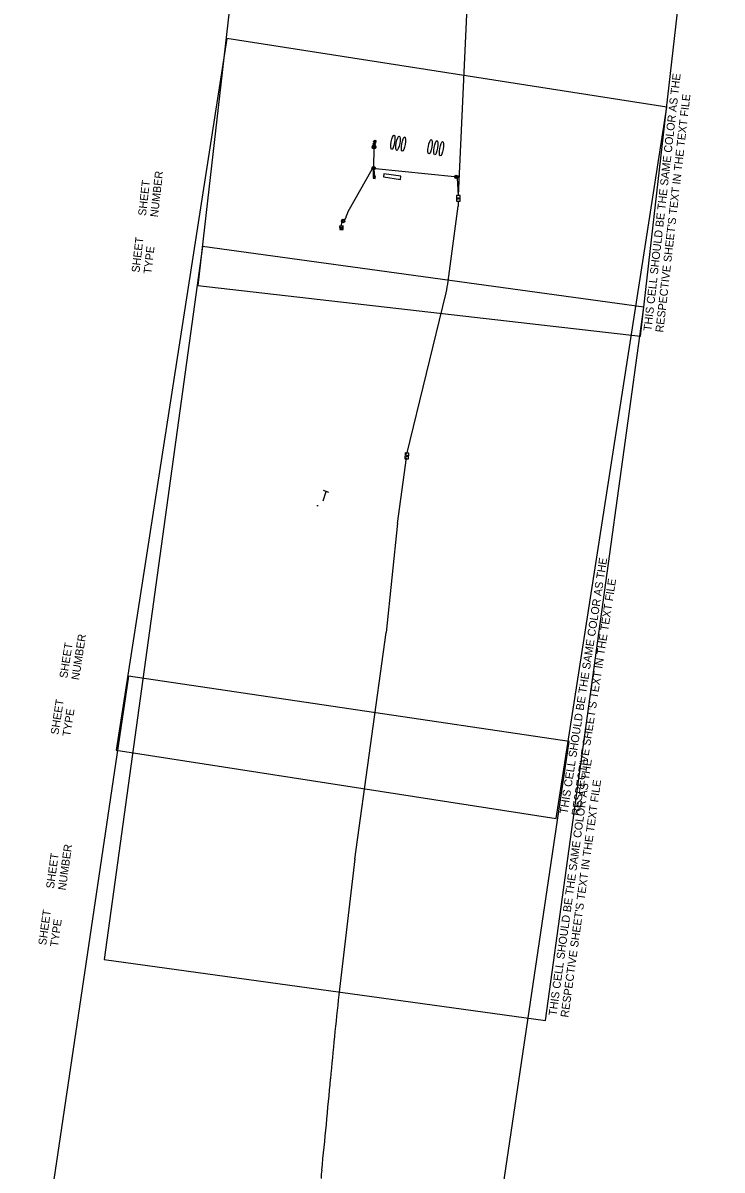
# Model space of a CAD drawing. Extents: x 601462 to 605493, y 331960 to 402715.
# Drawn here: x 601939 to 603469, y 358810 to 361319 of the extents above; entities that cross this region are included whole.
import ezdxf

# ---------------------------------------------------------------- set-up
doc = ezdxf.new("R2010")
doc.units = 0
for name, color, linetype in [('P_FTMS', 7, 'Continuous'), ('P_FTMSConduit', 7, 'Continuous'), ('P_MISC_TXT_1A (Construction)', 7, 'Continuous'), ('P_MISC_TXT_1B (Construction)', 7, 'Continuous'), ('P_MISC_TXT_2A (Construction)', 7, 'Continuous'), ('P_MISC_TXT_2B (Construction)', 7, 'Continuous')]:
    doc.layers.add(name, color=color, linetype=linetype)

# ---------------------------------------------------------------- blocks, each defined once
blk = doc.blocks.new('FTMS_FCV')
at = {"layer": 'P_FTMS'}
blk.add_line((13, 16), (1, -22), dxfattribs=at)
blk.add_lwpolyline([(39, 24), (-39, 24), (-39, -24), (39, -24)], close=True, dxfattribs=at)
blk.add_lwpolyline([(-12, 16), (1, -22)], dxfattribs=at)
blk = doc.blocks.new('FMB')
at = {"layer": 'P_FTMS'}
for p, q in [((24, -24), (-24, 24)), ((-24, -24), (24, 24))]:
    blk.add_line(p, q, dxfattribs=at)
blk.add_lwpolyline([(24, -24), (24, 24), (-24, 24), (-24, -24)], close=True, dxfattribs=at)
blk = doc.blocks.new('FMB_1')
at = {"layer": 'P_FTMS'}
for p, q in [((24, -24), (-24, 24)), ((-24, -24), (24, 24))]:
    blk.add_line(p, q, dxfattribs=at)
blk.add_lwpolyline([(24, -24), (24, 24), (-24, 24), (-24, -24)], close=True, dxfattribs=at)
blk = doc.blocks.new('_U238')
at = {"layer": 'P_FTMS'}
for points in [[(-15, -7), (7, -15), (0, 0)], [(15, 7), (-7, 15), (0, 0)]]:
    blk.add_lwpolyline(points, close=True, dxfattribs=at)
at = {"layer": 'P_FTMS', "xscale": 0.47132639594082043, "yscale": 0.4713263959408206, "rotation": 70.39802054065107}
blk.add_blockref('FMB_1', (0, 0), dxfattribs=at)
blk = doc.blocks.new('FTMS_FERA')
at = {"layer": 'P_FTMS'}
for p, q in [((-65, 37), (-65, -37)), ((65, 0), (-65, 0))]:
    blk.add_line(p, q, dxfattribs=at)
blk = doc.blocks.new('FMD')
at = {"layer": 'P_FTMS'}
for p, q in [((17, 18), (-17, 18)), ((-16, 16), (-16, 18)), ((16, 16), (-16, 16)), ((-15, 15), (-15, 20)), ((15, 19), (-15, 19)), ((15, 15), (-15, 15)), ((14, 20), (-14, 20)), ((13, 22), (-13, 22)), ((-13, 13), (-13, 21)), ((13, 13), (-13, 13)), ((-12, 12), (-12, 23)), ((12, 12), (-12, 12)), ((11, 23), (-11, 23)), ((10, 25), (-10, 25)), ((-10, 10), (-10, 24)), ((10, 10), (-10, 10)), ((-9, 9), (-9, 26)), ((9, 9), (-9, 9)), ((8, 26), (-8, 26)), ((7, 28), (-7, 28)), ((-7, 7), (-7, 27)), ((7, 7), (-7, 7)), ((-6, 6), (-6, 29)), ((6, 6), (-6, 6)), ((5, 29), (-5, 29)), ((4, 31), (-4, 31)), ((-4, 4), (-4, 30)), ((4, 4), (-4, 4)), ((-3, 3), (-3, 32)), ((3, 3), (-3, 3)), ((2, 32), (-2, 32)), ((1, 34), (-1, 34)), ((-1, 1), (-1, 33)), ((1, 1), (-1, 1)), ((0, 0), (0, 34)), ((1, 1), (1, 33)), ((3, 3), (3, 32)), ((4, 4), (4, 30)), ((6, 6), (6, 29)), ((7, 7), (7, 27)), ((9, 9), (9, 26)), ((10, 10), (10, 24)), ((12, 12), (12, 23)), ((13, 13), (13, 21)), ((15, 15), (15, 20)), ((16, 16), (16, 18))]:
    blk.add_line(p, q, dxfattribs=at)
blk.add_lwpolyline([(-17, 17), (0, 34), (17, 17), (0, 0)], close=True, dxfattribs=at)

msp = doc.modelspace()

# ---------------------------------------------------------------- linework, layer by layer
at = {"layer": 'P_FTMS'}
for p, q in [((602705.2, 361051.2), (602703.6, 361047.2)), ((602704.8, 361050.9), (602703.6, 361047.7)), ((602705.6, 361051.4), (602703.7, 361046.8)), ((602705.9, 361051.6), (602703.8, 361046.4)), ((602706.2, 361051.7), (602704, 361046.1)), ((602706.5, 361051.8), (602704.1, 361045.9)), ((602706.8, 361051.9), (602704.3, 361045.6)), ((602707.1, 361051.9), (602704.5, 361045.4)), ((602707.3, 361051.9), (602704.6, 361045.2)), ((602707.6, 361051.9), (602704.8, 361045)), ((602711.5, 361048.2), (602704.8, 361050.8)), ((602707.8, 361051.9), (602705, 361044.9)), ((602711.5, 361048.4), (602705, 361051)), ((602708.1, 361051.9), (602705.2, 361044.7)), ((602711.5, 361048.7), (602705.2, 361051.2)), ((602708.3, 361051.9), (602705.4, 361044.6)), ((602711.4, 361049), (602705.5, 361051.4)), ((602708.6, 361051.8), (602705.6, 361044.4)), ((602711.3, 361049.3), (602705.7, 361051.5)), ((602708.8, 361051.7), (602705.8, 361044.3)), ((602709, 361051.7), (602706.1, 361044.2)), ((602711.2, 361049.6), (602706.1, 361051.6)), ((602709.2, 361051.6), (602706.3, 361044.1)), ((602711, 361049.9), (602706.4, 361051.8)), ((602709.5, 361051.4), (602706.5, 361044.1)), ((602710.8, 361050.3), (602706.8, 361051.9)), ((602709.7, 361051.3), (602706.8, 361044)), ((602709.9, 361051.2), (602707, 361044)), ((602710.5, 361050.7), (602707.3, 361051.9)), ((602710.1, 361051), (602707.3, 361044)), ((602710.3, 361050.9), (602707.5, 361044)), ((602710, 361051.1), (602708, 361051.9)), ((602704.4, 361050.4), (602703.6, 361048.3)), ((602710.9, 361045.8), (602703.6, 361048.7)), ((602710.8, 361045.6), (602703.6, 361048.5)), ((602710.6, 361045.4), (602703.6, 361048.2)), ((602710.5, 361045.2), (602703.6, 361048)), ((602710.3, 361045), (602703.6, 361047.7)), ((602710.1, 361044.9), (602703.6, 361047.5)), ((602709.9, 361044.7), (602703.6, 361047.2)), ((602711.1, 361046), (602703.7, 361049)), ((602709.6, 361044.5), (602703.7, 361046.9)), ((602711.3, 361046.5), (602703.8, 361049.4)), ((602711.2, 361046.2), (602703.8, 361049.2)), ((602709.3, 361044.4), (602703.8, 361046.6)), ((602711.3, 361046.7), (602703.9, 361049.6)), ((602709.1, 361044.2), (602703.9, 361046.3)), ((602711.4, 361046.9), (602704.1, 361049.9)), ((602708.7, 361044.1), (602704.1, 361046)), ((602711.5, 361047.2), (602704.2, 361050.1)), ((602711.5, 361047.4), (602704.3, 361050.3)), ((602708.3, 361044), (602704.3, 361045.6)), ((602711.5, 361047.6), (602704.5, 361050.5)), ((602711.5, 361047.9), (602704.6, 361050.7)), ((602707.8, 361044), (602704.6, 361045.2)), ((602707.1, 361044), (602705.1, 361044.8)), ((602710.4, 361050.7), (602707.8, 361044)), ((602710.6, 361050.5), (602708, 361044)), ((602710.8, 361050.3), (602708.3, 361044)), ((602711, 361050), (602708.6, 361044.1)), ((602711.1, 361049.7), (602708.9, 361044.2)), ((602711.2, 361049.4), (602709.2, 361044.3)), ((602711.4, 361049.1), (602709.5, 361044.5)), ((602711.5, 361048.7), (602709.9, 361044.7)), ((602711.5, 361048.2), (602710.3, 361045)), ((602711.5, 361047.5), (602710.7, 361045.5)), ((602729.5, 360989.2), (602728.5, 360982.4)), ((602728.5, 360982.4), (602765.6, 360977.2)), ((602766.6, 360984.1), (602729.5, 360989.2)), ((602765.6, 360977.2), (602766.6, 360984.1))]:
    msp.add_line(p, q, dxfattribs=at)
msp.add_lwpolyline([(602728.5, 360982.4), (602765.6, 360977.2), (602766.6, 360984.1), (602729.5, 360989.2)], close=True, dxfattribs=at)
for centre, radius in [((602707.5, 361047.9), 4), ((602706.9, 361001.6), 3.75), ((602887.8, 360982.5), 3.75), ((602640.1, 360886.1), 3.75)]:
    msp.add_circle(centre, radius, dxfattribs=at)
for centre, start, end in [((602706.6, 360997.2), 32.6299, 138.8855), ((602707.3, 361006.1), 212.6299, 318.8855), ((602887.4, 360978), 32.6299, 138.8855), ((602888.1, 360987), 212.6299, 318.8855), ((602639.8, 360881.7), 32.6299, 138.8855), ((602640.5, 360890.6), 212.6299, 318.8855)]:
    msp.add_arc(centre, 3.75, start, end, dxfattribs=at)
for centre in [(602749, 361058.3), (602760.2, 361056.3), (602772.1, 361054.3), (602830.3, 361048.5), (602843, 361046.3), (602855.2, 361044.2)]:
    msp.add_ellipse(centre, major_axis=(-2.7, -15.7), ratio=0.23471, dxfattribs=at)
at = {"layer": 'P_FTMSConduit'}
for p, q in [((602707.4, 361005.6), (602707.7, 361043.9)), ((602710.7, 361001.3), (602884.2, 360983.5)), ((602706.2, 360998), (602705.5, 360982.9)), ((602707.3, 360997.9), (602708.7, 360984)), ((602892.8, 360942.1), (602890.6, 360980)), ((602636.3, 360875.3), (602637, 360884.1)), ((602758.9, 360224.5), (602778.7, 360367.9)), ((602585.7, 360263.4), (602582.6, 360263.1)), ((602758.9, 360224.9), (602734.1, 359986.4)), ((602665.6, 359490.5), (602734, 359985.8)), ((602665.7, 359490.9), (602630.7, 359193.4))]:
    msp.add_line(p, q, dxfattribs=at)
for points in [[(602892.8, 360942.1), (602911.3, 361353.5)], [(602650.9, 360907.2), (602703.8, 360999.6)], [(602892.4, 360930.1), (602892.4, 360929.2)], [(602870.2, 360754.7), (602892.2, 360918.3)], [(602779.4, 360375.8), (602865.3, 360729)]]:
    msp.add_lwpolyline(points, dxfattribs=at)
for centre, radius, start, end in [((602842.7, 360925), 50, 352.3262, 5.9193), ((602577.6, 360925.5), 75.6, 330.3744, 345.9697), ((602622.4, 360788.1), 250, 346.3228, 352.3262), ((610662.2, 358306.9), 8080.3, 173.70013, 175.00722), ((591535.1, 359977.9), 11119.7, 353.9728, 355.00722), ((602671.7, 358796.8), 79.5, 170.2547, 183.3334)]:
    msp.add_arc(centre, radius, start, end, dxfattribs=at)
at = {"layer": 'P_MISC_TXT_1A (Construction)'}
msp.add_lwpolyline([(603290.7, 360634.3), (603469.4, 362199.1), (602500.7, 362309.8), (602322, 360745)], close=True, dxfattribs=at)
at = {"layer": 'P_MISC_TXT_1B (Construction)'}
msp.add_lwpolyline([(603082.7, 359137.1), (603298.3, 360697.3), (602332.5, 360830.7), (602116.9, 359270.6)], close=True, dxfattribs=at)
at = {"layer": 'P_MISC_TXT_2A (Construction)'}
msp.add_lwpolyline([(602903.8, 358189.7), (603134.9, 359747.6), (602170.5, 359890.7), (601939.4, 358332.8)], close=True, dxfattribs=at)
at = {"layer": 'P_MISC_TXT_2B (Construction)'}
msp.add_lwpolyline([(603106.7, 359579), (603348.9, 361135.2), (602385.5, 361285.2), (602143.3, 359728.9)], close=True, dxfattribs=at)

# ---------------------------------------------------------------- block references
at = {"layer": 'P_FTMS'}
for name, p, xscale, yscale, rotation in [('FMD', (602705.6, 361055), 0.16404166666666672, 0.16404166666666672, -101.0974780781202), ('FMD', (602706.7, 361060.5), 0.16404166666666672, 0.16404166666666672, -101.0974780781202), ('_U238', (602708.4, 360981.7), 0.19684999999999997, 0.19684999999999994, 11.744108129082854), ('FTMS_FCV', (602892.5, 360935.7), 0.16404166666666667, 0.16404166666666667, 90.21124366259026), ('FMB', (602636.4, 360871.3), 0.16404166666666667, 0.16404166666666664, 91.21445292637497), ('FTMS_FCV', (602779.3, 360372.4), 0.1640416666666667, 0.16404166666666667, 86.34463929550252), ('FTMS_FERA', (602600, 360284.3), 0.16404166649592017, 0.16404143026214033, -107.86745926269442)]:
    msp.add_blockref(name, p, dxfattribs=dict(at, xscale=xscale, yscale=yscale, rotation=rotation))

# ---------------------------------------------------------------- texts
at = {"layer": 'P_MISC_TXT_1A (Construction)'}
for s, p in [('THIS CELL SHOULD BE THE SAME COLOR AS THE', (603314.6, 360644.6)), ("RESPECTIVE SHEET'S TEXT IN THE TEXT FILE", (603340.7, 360641.7)), ('SHEET', (602208.6, 360896.8)), ('NUMBER', (602234.7, 360893.8)), ('SHEET', (602194.4, 360772.6)), ('TYPE', (602220.5, 360769.6))]:
    msp.add_text(s, height=17.5, rotation=83.4833, dxfattribs=at).set_placement(p)
at = {"layer": 'P_MISC_TXT_1B (Construction)'}
for s, p in [('THIS CELL SHOULD BE THE SAME COLOR AS THE', (603106.9, 359146.8)), ("RESPECTIVE SHEET'S TEXT IN THE TEXT FILE", (603132.9, 359143.2)), ('NUMBER', (602033.1, 359421.4)), ('SHEET', (602007.1, 359425)), ('SHEET', (601990, 359301.2)), ('TYPE', (602016, 359297.6))]:
    msp.add_text(s, height=17.5, rotation=82.1325, dxfattribs=at).set_placement(p)
at = {"layer": 'P_MISC_TXT_2B (Construction)'}
for s, p in [('THIS CELL SHOULD BE THE SAME COLOR AS THE', (603131, 359588.3)), ("RESPECTIVE SHEET'S TEXT IN THE TEXT FILE", (603157, 359584.3)), ('NUMBER', (602062.1, 359881.2)), ('SHEET', (602036.2, 359885.2)), ('SHEET', (602017, 359761.7)), ('TYPE', (602042.9, 359757.7))]:
    msp.add_text(s, height=17.5, rotation=81.1528, dxfattribs=at).set_placement(p)

doc.saveas('drawing.dxf')
